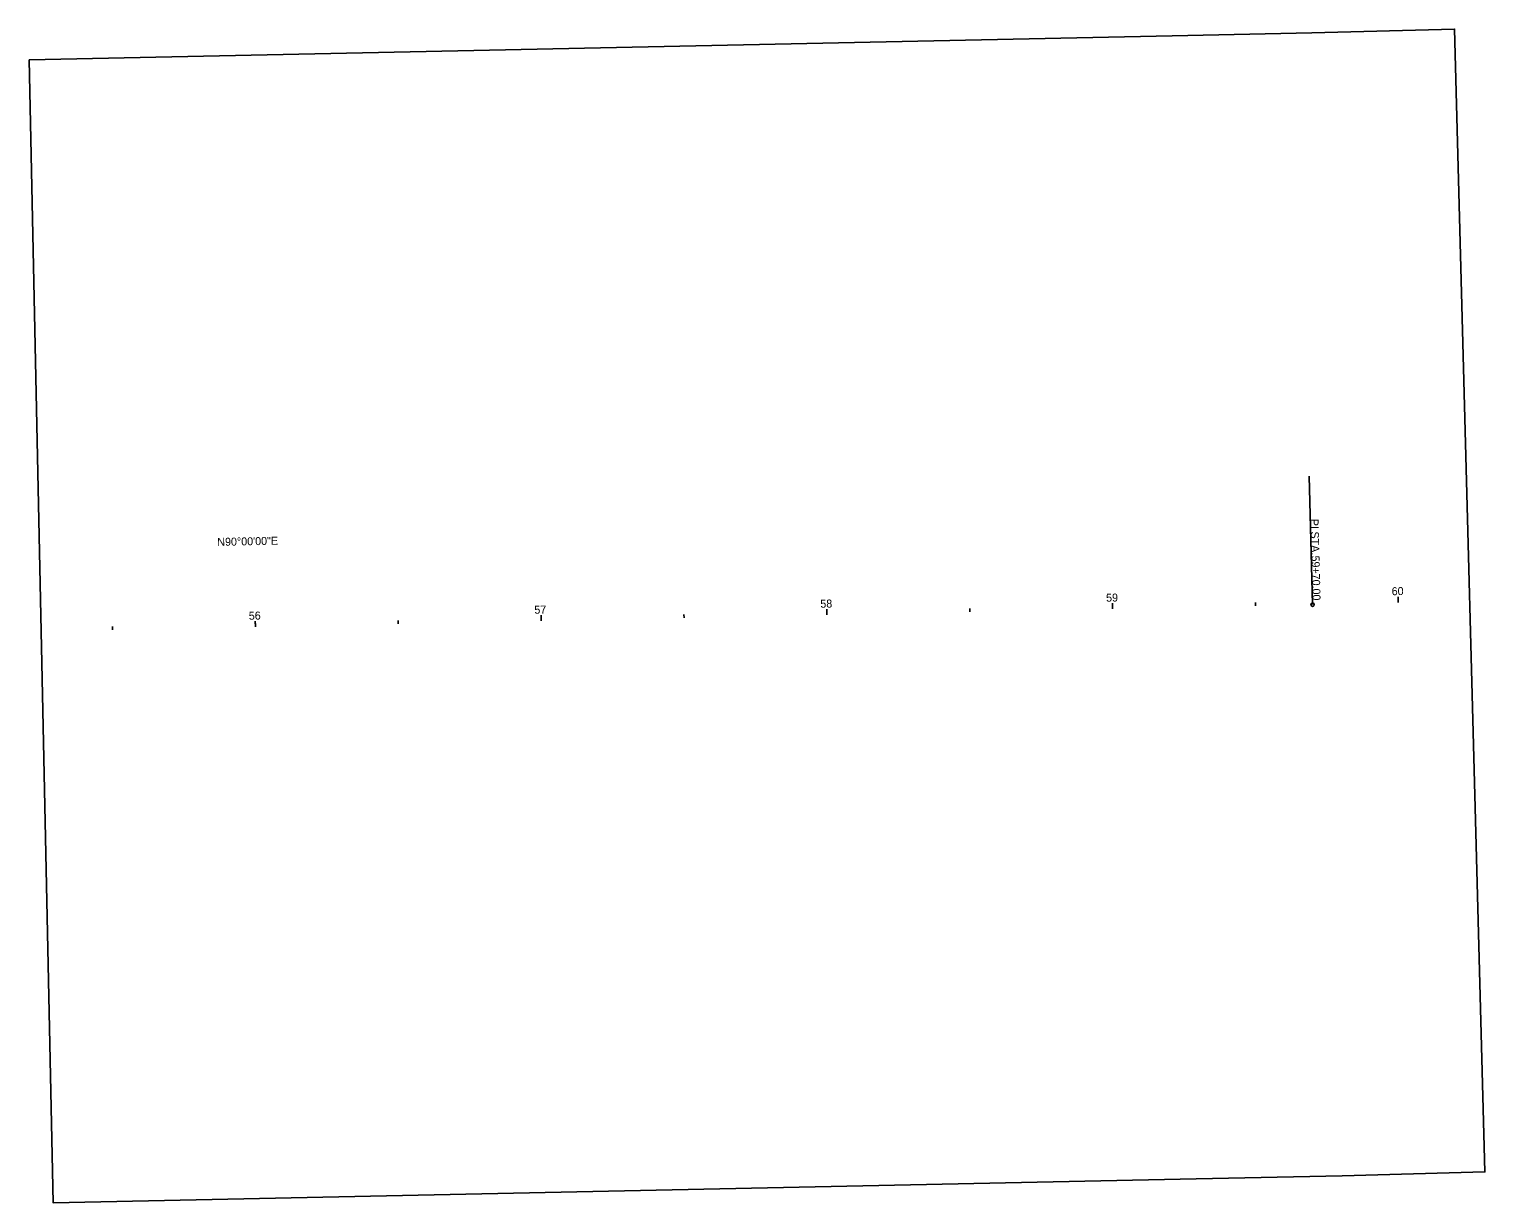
# Model space of a CAD drawing. Extents: x 2402033 to 2407435, y 498456 to 498900.
# Drawn here: x 2402555 to 2403065, y 498456 to 498867 of the extents above; entities that cross this region are included whole.
import ezdxf

# ---------------------------------------------------------------- set-up
doc = ezdxf.new("R2010")
doc.units = 0
for name, color, linetype in [('DR_P_Ditch', 7, 'Continuous'), ('DV_X_Property_Line', 7, 'Continuous'), ('RW_P_Esmt_CH', 7, 'Continuous'), ('RW_P_Esmt_SH', 7, 'Continuous'), ('RW_X_CL_100_Distances', 7, 'Continuous'), ('RW_X_Esmt_SH', 7, 'Continuous'), ('RW_X_Parent_Tract_Area', 7, 'Continuous'), ('SH_Named_Boundary', 7, 'Continuous')]:
    doc.layers.add(name, color=color, linetype=linetype)

msp = doc.modelspace()

# ---------------------------------------------------------------- linework, layer by layer
at = {"layer": 'DR_P_Ditch'}
msp.add_line((2403034.46, 498666.61), (2403034.41, 498668.61), dxfattribs=at)
at = {"layer": 'DV_X_Property_Line'}
msp.add_line((2403004.47, 498665.82), (2403003.28, 498710.8), dxfattribs=at)
msp.add_circle((2403004.47, 498665.82), 0.6, dxfattribs=at)
at = {"layer": 'RW_P_Esmt_CH'}
for p, q in [((2403034.46, 498666.61), (2403034.41, 498668.61)), ((2402834.51, 498662.24), (2402834.49, 498663.44)), ((2402934.49, 498664.35), (2402934.46, 498665.55)), ((2402634.56, 498658.03), (2402634.53, 498659.23)), ((2402734.53, 498660.14), (2402734.51, 498661.34))]:
    msp.add_line(p, q, dxfattribs=at)
at = {"layer": 'RW_P_Esmt_SH'}
msp.add_line((2403004.47, 498665.82), (2403003.28, 498710.8), dxfattribs=at)
msp.add_circle((2403004.47, 498665.82), 0.6, dxfattribs=at)
at = {"layer": 'RW_X_Esmt_SH'}
for p, q in [((2403034.46, 498666.61), (2403034.41, 498668.61)), ((2402734.53, 498660.14), (2402734.49, 498662.14)), ((2402784.52, 498661.19), (2402784.5, 498662.39)), ((2402834.51, 498662.24), (2402834.47, 498664.24)), ((2402884.5, 498663.3), (2402884.47, 498664.49)), ((2402934.49, 498664.35), (2402934.45, 498666.35)), ((2402984.48, 498665.4), (2402984.45, 498666.6)), ((2402584.57, 498656.98), (2402584.54, 498658.18)), ((2402634.56, 498658.03), (2402634.51, 498660.03)), ((2402684.54, 498659.09), (2402684.52, 498660.29))]:
    msp.add_line(p, q, dxfattribs=at)
at = {"layer": 'RW_X_Parent_Tract_Area'}
msp.add_line((2403004.47, 498665.82), (2403003.28, 498710.8), dxfattribs=at)
msp.add_circle((2403004.47, 498665.82), 0.6, dxfattribs=at)
at = {"layer": 'SH_Named_Boundary'}
msp.add_lwpolyline([(2402555.36, 498856.41), (2402563.78, 498456.5), (2402613.77, 498457.55), (2402663.76, 498458.6), (2402713.75, 498459.66), (2402763.74, 498460.71), (2402813.73, 498461.76), (2402863.71, 498462.81), (2402913.7, 498463.87), (2402963.69, 498464.92), (2403014.76, 498466.02), (2403064.75, 498467.35), (2403054.16, 498867.21), (2403004.18, 498865.88), (2402955.27, 498864.83), (2402905.29, 498863.78), (2402855.3, 498862.72), (2402805.31, 498861.67), (2402755.32, 498860.62), (2402705.33, 498859.57), (2402655.34, 498858.52), (2402605.35, 498857.46)], close=True, dxfattribs=at)

# ---------------------------------------------------------------- texts
at = {"layer": 'DR_P_Ditch'}
msp.add_text('60', height=2.8, rotation=1.5166, dxfattribs=at).set_placement((2403032.17, 498669.1))
at = {"layer": 'DV_X_Property_Line'}
for s, p in [('PI', (2403003.72, 498695.81)), (' STA. ', (2403003.81, 498692.42)), ('59+70.00', (2403004.06, 498682.97))]:
    msp.add_text(s, height=2.8, rotation=271.5166, dxfattribs=at).set_placement(p)
at = {"layer": 'RW_P_Esmt_CH'}
msp.add_text('60', height=2.8, rotation=1.5166, dxfattribs=at).set_placement((2403032.17, 498669.1))
at = {"layer": 'RW_P_Esmt_SH'}
for s, p in [('PI', (2403003.72, 498695.81)), (' STA. ', (2403003.81, 498692.42)), ('59+70.00', (2403004.06, 498682.97))]:
    msp.add_text(s, height=2.8, rotation=271.5166, dxfattribs=at).set_placement(p)
at = {"layer": 'RW_X_CL_100_Distances'}
msp.add_text('N90°00\'00"E', height=2.8, rotation=1.2059, dxfattribs=at).set_placement((2402621.24, 498686.36))
at = {"layer": 'RW_X_Esmt_SH'}
for s, rotation, p in [('58', 1.2059, (2402832.24, 498664.74)), ('59', 1.2059, (2402932.23, 498666.84)), ('60', 1.5166, (2403032.17, 498669.1)), ('56', 1.2059, (2402632.26, 498660.53)), ('57', 1.2059, (2402732.18, 498662.63))]:
    msp.add_text(s, height=2.8, rotation=rotation, dxfattribs=at).set_placement(p)
at = {"layer": 'RW_X_Parent_Tract_Area'}
for s, p in [('PI', (2403003.72, 498695.81)), (' STA. ', (2403003.81, 498692.42)), ('59+70.00', (2403004.06, 498682.97))]:
    msp.add_text(s, height=2.8, rotation=271.5166, dxfattribs=at).set_placement(p)

doc.saveas('drawing.dxf')
